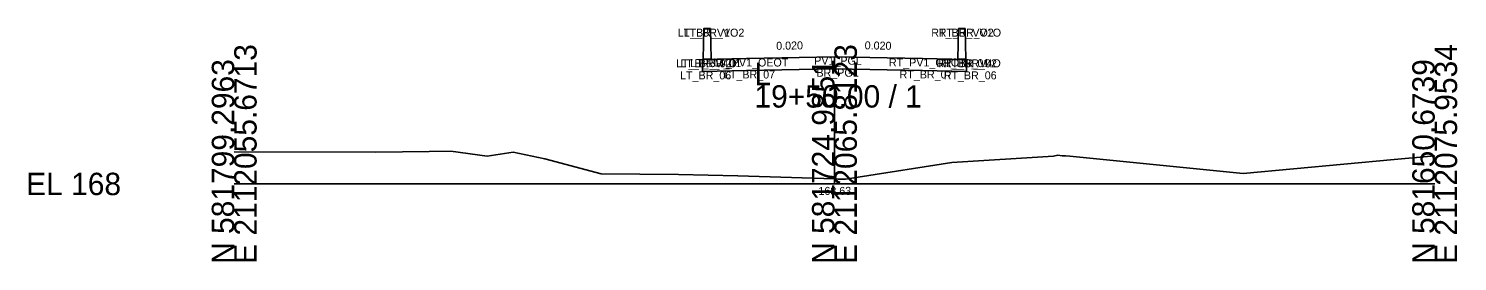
# Model space of a CAD drawing. Extents: x -486 to 1153, y -333 to 9539.
# Drawn here: x 974.3 to 1152.8, y 490.3 to 519.4 of the extents above; entities that cross this region are included whole.
import ezdxf

# ---------------------------------------------------------------- set-up
doc = ezdxf.new("R2010")
doc.units = 0
for name, color, linetype in [('Default', 7, 'Continuous'), ('Exist Cross Section Cell', 7, 'Continuous'), ('Exist XS Ground Line', 7, 'Continuous'), ('Prop CMT Concrete Structures', 7, 'Continuous'), ('Prop XS SE Text', 7, 'Continuous'), ('Scratch_Level_0', 7, 'Continuous')]:
    doc.layers.add(name, color=color, linetype=linetype)

msp = doc.modelspace()

# ---------------------------------------------------------------- linework, layer by layer
at = {"layer": 'Exist Cross Section Cell'}
for p, q in [((1075, 500), (1075, 512.35)), ((1000, 500), (1075, 500)), ((1075, 500), (1150, 500))]:
    msp.add_line(p, q, dxfattribs=at)
at = {"layer": 'Exist XS Ground Line'}
for p, q in [((1000, 504.02), (1017.71, 503.96)), ((1017.71, 503.96), (1024.34, 504.07)), ((1024.34, 504.07), (1027.08, 504.12)), ((1027.08, 504.12), (1031.6, 503.48)), ((1031.6, 503.48), (1034.84, 503.96)), ((1034.84, 503.96), (1038.83, 503.13)), ((1089.68, 502.67), (1102.39, 503.49)), ((1102.39, 503.49), (1102.92, 503.6)), ((1102.92, 503.6), (1103.46, 503.53)), ((1103.46, 503.53), (1103.89, 503.51)), ((1103.89, 503.51), (1104.43, 503.46)), ((1144.95, 503.05), (1150, 503.52)), ((1038.83, 503.13), (1045.87, 501.28)), ((1077.97, 500.85), (1089.68, 502.67)), ((1104.43, 503.46), (1126.06, 501.32)), ((1126.06, 501.32), (1144.95, 503.05)), ((1045.87, 501.28), (1055.53, 501.18)), ((1055.53, 501.18), (1062.93, 501.01)), ((1062.93, 501.01), (1075, 500.63)), ((1075, 500.63), (1075.47, 500.61)), ((1075.47, 500.61), (1076.36, 500.6)), ((1076.36, 500.6), (1077.97, 500.85))]:
    msp.add_line(p, q, dxfattribs=at)
at = {"layer": 'Prop CMT Concrete Structures'}
for points in [[(1059.58, 515.61), (1059.5, 519.42), (1058.67, 519.42), (1058.58, 515.59)], [(1090.42, 515.61), (1090.5, 519.42), (1091.33, 519.42), (1091.42, 515.59)], [(1075, 515.91), (1064, 515.69), (1058.5, 515.58)], [(1058.5, 515.58), (1058.5, 514.08)], [(1058.5, 514.08), (1064, 514.19), (1075, 514.41)], [(1058.58, 515.59), (1059.58, 515.61)], [(1075, 514.41), (1075, 515.91)], [(1075, 515.91), (1086, 515.69), (1091.5, 515.58)], [(1075, 514.41), (1075, 515.91)], [(1091.5, 514.08), (1086, 514.19), (1075, 514.41)], [(1091.42, 515.59), (1090.42, 515.61)], [(1091.5, 515.58), (1091.5, 514.08)]]:
    msp.add_lwpolyline(points, dxfattribs=at)

# ---------------------------------------------------------------- texts
at = {"layer": 'Default'}
for s, height, p in [('-', 0.0001, (1000, 500)), ('168.63', 1, (1073, 498.63))]:
    msp.add_text(s, height=height, dxfattribs=at).set_placement(p)
at = {"layer": 'Exist Cross Section Cell'}
for s, p in [('E 2112055.6713', (1002.8, 490)), ('E 2112065.8123', (1077.8, 490)), ('E 2112075.9534', (1152.8, 490)), ('N 581799.2963', (1000, 490)), ('N 581724.9851', (1075, 490)), ('N 581650.6739', (1150, 490))]:
    msp.add_text(s, height=2.8, rotation=90, dxfattribs=at).set_placement(p)
for s, p in [('L', (1065, 512.35)), ('19+50.00 / 1', (1065, 509.55)), ('EL 168', (974, 498.6))]:
    msp.add_text(s, height=2.8, dxfattribs=at).set_placement(p)
at = {"layer": 'Prop XS SE Text'}
for rotation, p in [(1.1458, (1067.73, 516.77)), (358.8542, (1078.77, 516.84))]:
    msp.add_text('0.020', height=1, rotation=rotation, dxfattribs=at).set_placement(p)
at = {"layer": 'Scratch_Level_0'}
for s, p in [('LT_BR_V1O', (1055.41, 518.42)), ('LT_BR_VO2', (1056.16, 518.42)), ('RT_BR_VO2', (1087.1, 518.42)), ('RT_BR_V1O', (1088.02, 518.42)), ('LT_BR_V4O', (1055.21, 514.59)), ('LT_BR_02', (1055.74, 514.58)), ('LT_BR_01', (1056.97, 514.61)), ('LT_PV1_OEOT', (1059.87, 514.69)), ('LT_BR_07', (1061.19, 513.19)), ('PV1_PGL', (1072.47, 514.91)), ('BR_PGL', (1072.75, 513.41)), ('RT_PV1_OEOT', (1081.81, 514.69)), ('RT_BR_07', (1083.14, 513.19)), ('RT_BR_01', (1087.74, 514.61)), ('RT_BR_V4O', (1087.98, 514.59)), ('RT_BR_02', (1088.68, 514.58)), ('LT_BR_06', (1055.71, 513.08)), ('RT_BR_06', (1088.65, 513.08))]:
    msp.add_text(s, height=1, dxfattribs=at).set_placement(p)

doc.saveas('drawing.dxf')
